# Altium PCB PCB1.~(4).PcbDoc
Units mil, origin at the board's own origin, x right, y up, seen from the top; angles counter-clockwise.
Board outline 1575 x 2765 mil, 2 copper layers (Top Layer, Bottom Layer); 15 components, 10 nets, 36 pads, 0 vias.
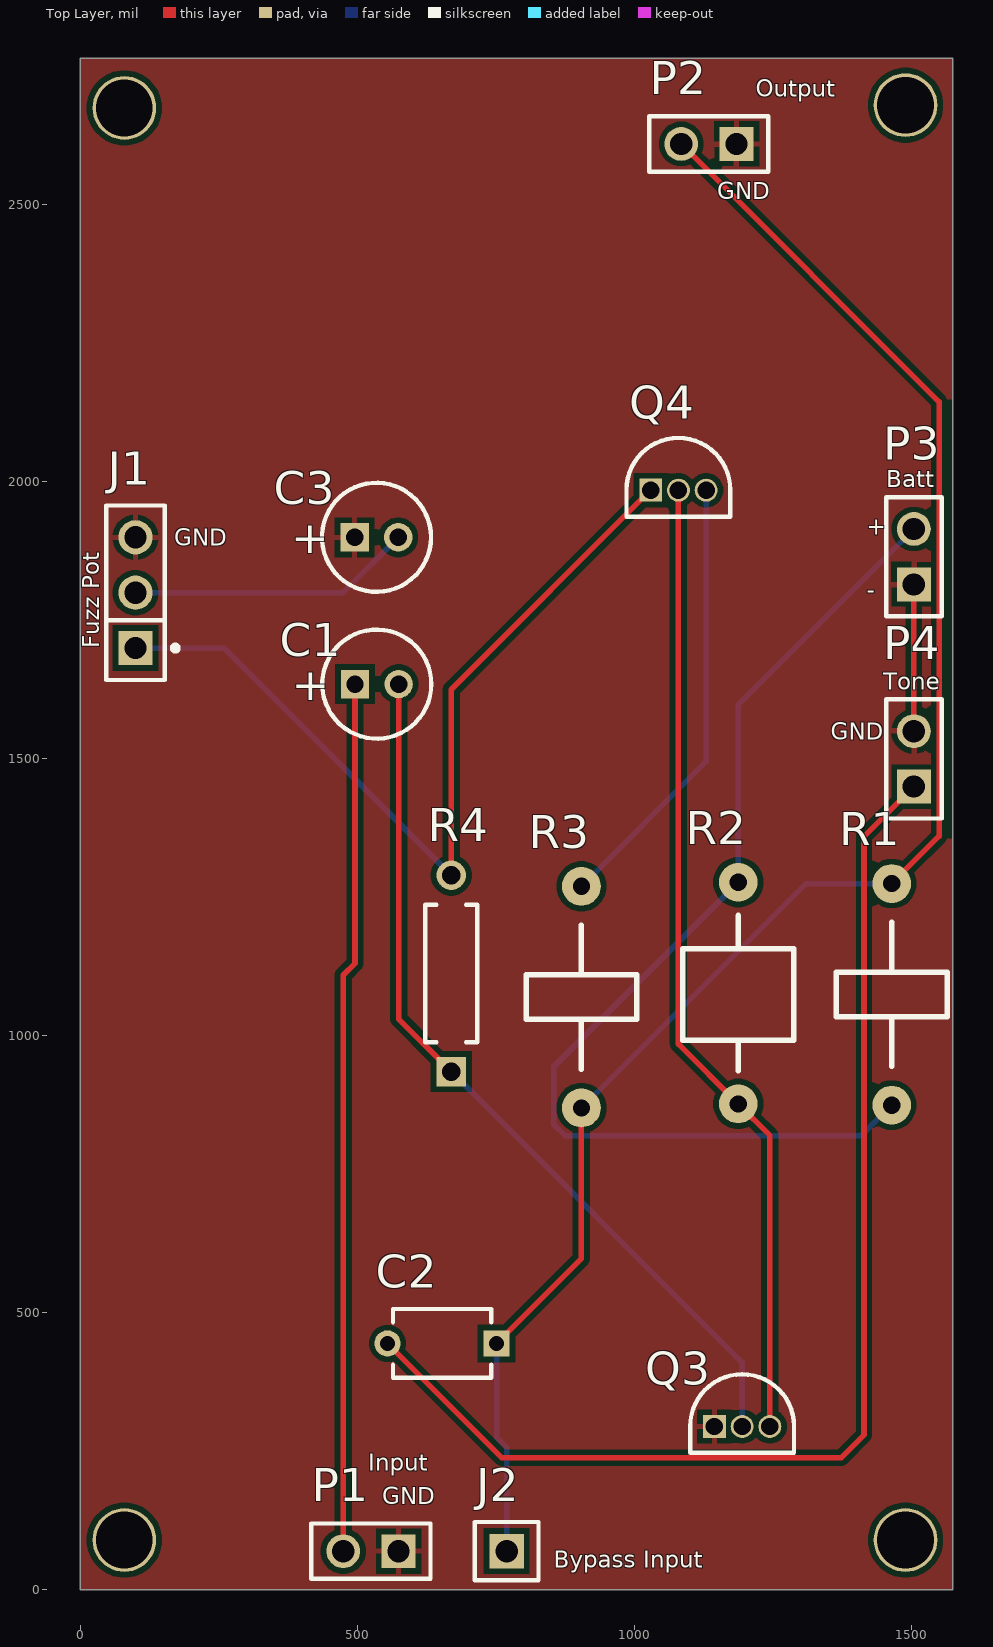
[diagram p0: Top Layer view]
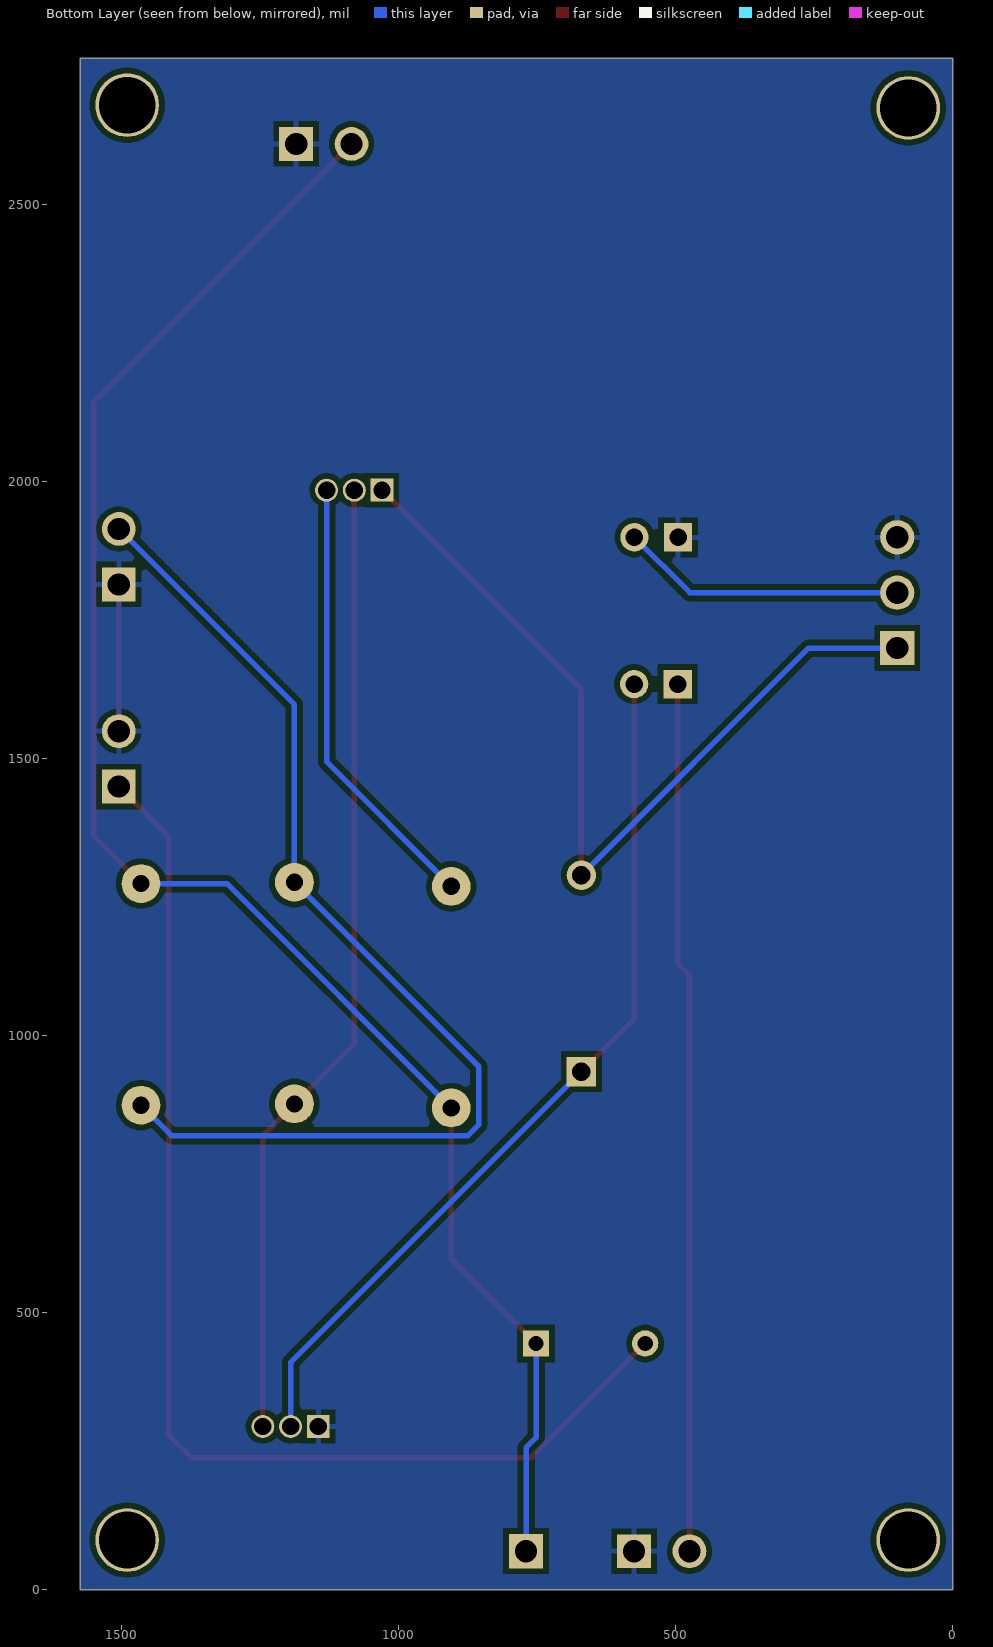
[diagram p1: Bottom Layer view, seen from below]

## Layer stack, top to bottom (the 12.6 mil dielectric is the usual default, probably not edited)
Top Solder: solder mask 0.4, Solder Resist, Dk 3.5
Top Layer: signal copper 1.4
Dielectric 1: dielectric 12.6, FR-4, Dk 4.8
Bottom Layer: signal copper 1.4
Bottom Solder: solder mask 0.4, Solder Resist, Dk 3.5

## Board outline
0,0 1575,0 1575,2765 0,2765

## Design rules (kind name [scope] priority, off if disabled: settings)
Clearance [All] p1: gap=10 ignorepadtopadclearanceinfootprint=FALSE
PolygonConnect [All] p1: connectstyle=Relief reliefconductorwidth=10 reliefentries=4 polygonreliefangle="90 Angle" airgapwidth=10
RoutingVias [All] p1: holewidth=28 width=50 viastyle="Through Hole" minholewidth=28 minwidth=50 maxholewidth=28 maxwidth=50
SolderMaskExpansion [All] p1: expansion=4 istentingtop=FALSE
SupplyNets "Schematic Supply Nets" [InNet('GND')] p1: voltage=0.000
Width [All] p1: maxlimit=10 minlimit=10 preferedwidth=10
30 further rules are at their usual default settings.

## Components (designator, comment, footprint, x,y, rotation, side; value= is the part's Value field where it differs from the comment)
C1 "ECA1HM2R2" CAPPR55-200-1100X500X1200 535.63,1635 r0 top value=2.2µF
C2 "RDER72H103K1K1H03B" FP-RDE1K1-MFG 653.43,445 r180 top
C3 "ECA1HM220" CAPPR55-200-1100X500X1200 535,1900 r0 top value=22µF
J1 "TSW-103-14-G-S" FP-TSW-103-14-G-S-MFG 100,1800 r90 top
J2 "TSW-101-07-F-S" FP-TSW-101-07-F-S-MFG 770,70 r0 top
P1 "TSW-102-26-G-S" SMTC-TSW-102-26-XX-S 575,70 r180 top
P2 "TSW-102-26-G-S" SMTC-TSW-102-26-XX-S 1185,2610 r180 top
P3 "TSW-102-26-G-S" SMTC-TSW-102-26-XX-S 1505,1815 r90 top
P4 "TSW-102-26-G-S" SMTC-TSW-102-26-XX-S 1505,1450 r90 top
Q3 "2N3904BU" FAIR-TO-92 1145,295 r0 top
Q4 "2N3904BU" FAIR-TO-92 1030,1985 r0 top
R1 "470 Ohm Generic Resistor" "470 Ohm Resistor" 1465,875 r90 top value=470
R2 "33K Ohm Generic Through Hole Resistor" "Resistor 33K ohm" 1188.07,877.37 r90 top value=33k
R3 "820 Ohm Generic Resistor" "Resistor 820 Ohm Generic" 905,870 r90 top value=820
R4 "MFR-25FBF52-100K" RESA60-630X240 670,1112.83 r90 top value=100k

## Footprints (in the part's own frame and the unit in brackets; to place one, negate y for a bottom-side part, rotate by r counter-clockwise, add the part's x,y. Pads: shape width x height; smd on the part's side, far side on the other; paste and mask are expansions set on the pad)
"470 Ohm Resistor" [mil]
  round 70 hole 31: 1(0,0) 2(400,0)
  silkscreen extent 70,-100 330,100
CAPPR55-200-1100X500X1200 [mm] "THD, 2-Leads, Dia 5mm, Pin Spacing 2mm"
  rect 1.3x1.3 hole 0.8: 1(-1,0)
  round 1.3 hole 0.8: 2(1,0)
  silkscreen extent -2.5,-2.5 2.5,2.5, body extent -2.5,-2.5 2.45,2.5, height 12
FAIR-TO-92 [mm] "TO, 3-Leads, Body Dia 4.79mm, Pitch 1.27mm"
  rect 1.05x1.05 hole 0.8 mask+0.05: 1(0,0)
  round 1.05 hole 0.8 mask+0.05: 2(1.27,0) 3(2.54,0)
  silkscreen extent -1.11,-1.21 3.65,2.4, body extent -1.11,-1.21 3.65,2.4, height 5.33
FP-RDE1K1-MFG [mm]
  rect 1.2x1.2 hole 0.7 paste-2539.97 mask+0: 1(-2.5,0)
  round 1.2 hole 0.7 paste-2539.97 mask+0: 2(2.5,0)
  silkscreen extent -2.25,-1.58 2.25,1.58, body extent -3.2,-1.68 3.2,1.68, height 0.25
FP-TSW-101-07-F-S-MFG [mm]
  rect 1.57x1.57 hole 1.02 paste-2539.97 mask+0: 1(0,0)
  silkscreen extent -1.46,-1.34 1.46,1.34, body extent -1.56,-1.44 1.56,1.44, height 0.25
FP-TSW-103-14-G-S-MFG [mm]
  rect 1.57x1.57 hole 1.02 paste-2539.97 mask+0: 1(-2.54,0)
  round 1.57 hole 1.02 paste-2539.97 mask+0: 2(0,0) 3(2.54,0)
  silkscreen extent -4,-1.95 4,1.34, body extent -4.1,-1.44 4.1,1.44, height 0.25
RESA60-630X240 [mm] "Axial Resistor, 2-Leads, Dia 2.4mm, Body Length 6.3mm"
  rect 1.35x1.35 hole 0.85: 1(-4.5,0)
  round 1.35 hole 0.85: 2(4.5,0)
  silkscreen extent -3.15,-1.2 3.15,1.2, body extent -4.77,-1.19 4.77,1.2, height 2.4
"Resistor 33K ohm" [mil]
  round 70 hole 31: 1(0,0) 2(400,0)
  silkscreen extent 60,-100 340,100
"Resistor 820 Ohm Generic" [mil]
  round 70 hole 31: 1(0,0) 2(400,0)
  silkscreen extent 70,-100 330,100
SMTC-TSW-102-26-XX-S [mm] ".025 SQ Post Terminal Strip Assembly, 1x2 Pins, Vertical, 2.54mm Pitch, Male"
  rect 1.55x1.55 hole 1.02: 1(0,0)
  round 1.55 hole 1.02: 2(2.54,0)
  silkscreen extent -1.46,-1.27 4,1.27, body extent -1.4,-1.27 3.81,1.27, height 8.38

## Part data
C1: library part CMP-001-00029-7, "Aluminum Electrolytic Capacitor, 2.2 uF, +/- 20%, 50 V, -40 to 85 degC, 2-Pin THD, RoHS, Bulk", Capacitor Type=Electrolytic, Case/Package=Radial, Manufacturer=Panasonic, Max Operating Temperature=85°C, Min Operating Temperature=-40°C, Package Description="2-Pin Radial Lead, Dia 5 mm, Height 12 mm", Package Quantity=200, Package Reference=CAPPR55-200-1100X500X1200, Ripple Current=20mA, Tolerance=20%, Voltage Rating=50V
C2: library part CMP-06035-024341-1, "Ceramic Capacitor 10nF ±10% 500V X7R Radial"
C3: library part CMP-001-00027-7, "Aluminum Electrolytic Capacitor, 22 uF, +/- 20%, 50 V, -40 to 85 degC, 2-Pin THD, RoHS, Bulk", Capacitor Type=Electrolytic, Case/Package=Radial, Manufacturer=Panasonic, Max Operating Temperature=85°C, Min Operating Temperature=-40°C, Package Description="2-Pin Radial Lead, Dia 5 mm, Height 12 mm", Package Quantity=200, Package Reference=CAPPR55-200-1100X500X1200, Ripple Current=100mA, Tolerance=20%, Voltage Rating=50V
J1: library part CMP-02766-001743-1, "CONN HEADER VERT 3POS 2.54MM", Color=Black, Flammability Rating="UL94 V-0", Max Current Rating=7.6A, Max Operating Temperature=125°C, Max Voltage Rating (AC)=550V, Min Operating Temperature=-55°C, Package Quantity=1
J2: library part CMP-02766-001403-1, "CONN HEADER VERT 1POS", Flammability Rating="UL94 V-0", Insulation Color=Black, Max Operating Temperature=125°C, Min Operating Temperature=-55°C
P1 P2 P3 P4: library part CMP-1024-00327-1, "0.025\" SQ Post Header, Through-hole, Vertical, -55 to 125 degC, 2.54 mm Pitch, 2-Pin, Male, RoHS", Manufacturer=Samtec, Temperature Range="-55 to 125 degC"
Q3 Q4: library part CMP-2000-04944-1, "NPN General-Purpose Amplifier, 40 V VCEO, 0.2 A, -55 to 150 degC, 2-Pin TO-92, RoHS, Bulk", Manufacturer=FairchildSemiconductor, Maximum Collector Base Voltage=60V, Maximum Collector Emitter Saturation Voltage=0.2@1mA@10mA, Maximum Collector Emitter Voltage=40V, Maximum DC Collector Current=0.2A, Maximum Operating Frequency=300(Min)MHz, Maximum Power Dissipation=625mW, Minimum DC Current Gain=40@0.1mA@1V, Operating Temperature=-55to150degC, Package=3TO-92, Package Description="3-Pin Transistor Outline Package, Body Dia 4.79 mm, Pitch 1.27 mm", Package Reference=TO-92
R1: library part CMP-009-00178-1, Power=250mW
R2: library part CMP-009-00177-1, Power=250mW
R3: library part CMP-009-00179-1, Power=250mW
R4: library part CMP-009-00045-4, "Axial Resistor, 100 KOhm, +/- 1%, 0.25 W, -55 to 155 degC, 2-Pin THD, RoHS, Bulk", Case/Package=Axial, Manufacturer=Yageo, Max Operating Temperature=155°C, Min Operating Temperature=-55°C, Package Description="2-Pin Axial Lead, Dia 2.4 mm, Body Length 6.3 mm", Package Quantity=200, Package Reference=MFR-25, Power=250mW, Tolerance=1%, Voltage Rating=250V

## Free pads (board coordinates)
  round 115 hole 102.36 unplated: 2(1490,2680) 3(1490,90) 32123(80,2675)
  round 115 hole 102.36: 4(80,90)

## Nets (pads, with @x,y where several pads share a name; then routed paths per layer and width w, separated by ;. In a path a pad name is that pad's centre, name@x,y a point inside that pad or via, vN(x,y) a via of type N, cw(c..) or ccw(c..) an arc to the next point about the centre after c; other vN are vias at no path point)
GND: C3.1 J1.3 P1.1 P2.1 P3.1 P4.2 Q3.1 | length 265
  Top Layer w10: P4.2 P3.1
NetC1_1: C1.1 P1.2 | length 1573.8
  Top Layer w10: P1.2 475,1109.74 496.26,1131 C1.1
NetC1_2: C1.2 Q3.2 R4.1 | length 1596.8
  Top Layer w10: C1.2 575,1030.67 R4.1
  Bottom Layer w10: R4.1 1195,410.67 Q3.2
NetC2_1: C2.1 J2.1 P2.2 R1.2 R3.1 | length 3154.9
  Top Layer w10: C2.1 905,598.15 R3.1 ; P2.2@1090,2605 1550.51,2144.49 1550.51,1360.51 R1.2
  Bottom Layer w10: C2.1 751.85,275.15 770,257 J2.1 ; R3.1 1310,1275 R1.2
NetC2_2: C2.2 P4.1 | length 2169.6
  Top Layer w10: C2.2 761,239 1374,239 1415,280 1415,1360 P4.1
NetC3_2: C3.2 J1.2 | length 515.8
  Bottom Layer w10: J1.2 474.37,1800 C3.2
NetJ1_1: J1.1 Q4.1 R4.2 | length 1583.9
  Top Layer w10: R4.2 670,1625 Q4.1
  Bottom Layer w10: J1.1 260,1700 R4.2
NetP3_2: P3.2 R1.1 R2.2 | length 1985.3
  Bottom Layer w10: R1.1 1410,820 875,820 855,840 855,944.3 R2.2 1188.07,1598.07 P3.2
NetQ3_3: Q3.3 Q4.2 R2.1 | length 1758.3
  Top Layer w10: Q4.2 1080,985.44 R2.1 1245,820.44 Q3.3
NetQ4_3: Q4.3 R3.2 | length 808.2
  Bottom Layer w10: R3.2 1130,1495 Q4.3

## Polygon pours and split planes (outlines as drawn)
GND on Bottom Layer "GND_L02_P000" (solid, pour order 0): 0,0 1575,0 1575,2765 0,2765 0,2760
GND on Top Layer "GND_L01_P001" (solid, pour order 1): 0,0 1575,0 1575,2765 0,2765 0,2760

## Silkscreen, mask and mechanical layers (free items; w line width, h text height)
Top Overlay:
  text "Output" at 1220,2695 h30
  text "GND" at 1150,2510 h30
  text "Batt" at 1455,1990 h30
  text "+" at 1420,1905 h30
  text "GND" at 170,1885 h30
  text "-" at 1420,1790 h30
  text "-" at -610,1775 h30
  text "Fuzz Pot" at 35,1700 h30 r90
  text "Tone" at 1450,1625 h30
  text "GND" at 1695,1575 h30
  text "GND" at 1355,1535 h30
  text "Input" at 520,215 h30
  text "GND" at 545,155 h30
  text "Bypass Input" at 855,40 h30

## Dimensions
1490,90 to 1490,2680 on Top Overlay
80,90 to 1490,90 on Top Overlay
80,2675 to 1490,2680 on Top Overlay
